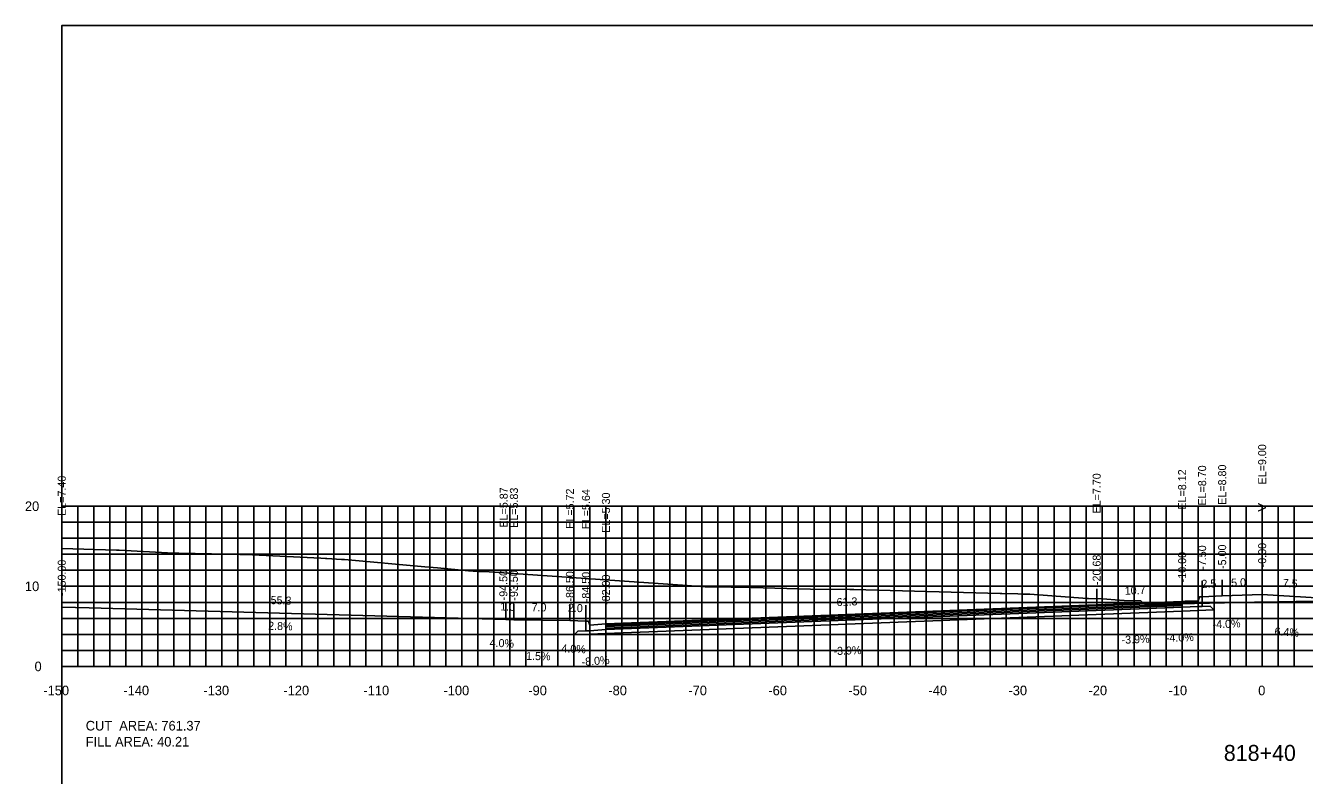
# Model space of a CAD drawing. Extents: x 1797419 to 1809236, y 248759 to 251512.
# Drawn here: x 1805536.5 to 1805696.3, y 250175.8 to 250269.4 of the extents above; entities that cross this region are included whole.
import ezdxf

# ---------------------------------------------------------------- set-up
doc = ezdxf.new("R2010")
doc.units = 0
for name, color, linetype in [('1', 7, 'Continuous'), ('10', 7, 'Continuous'), ('3', 7, 'Continuous'), ('31', 7, 'Continuous'), ('4', 7, 'Continuous'), ('60', 7, 'Continuous'), ('ANNO-TXT', 7, 'Continuous'), ('BASE', 7, 'Continuous'), ('CL-CNST', 7, 'Continuous'), ('Level 62', 7, 'Continuous'), ('LOWER BINDER', 7, 'Continuous'), ('M-ROADS', 7, 'Continuous'), ('UPPER BINDER', 7, 'Continuous'), ('WEARING', 7, 'Continuous')]:
    doc.layers.add(name, color=color, linetype=linetype)

msp = doc.modelspace()

# ---------------------------------------------------------------- linework, layer by layer
for p, q in [((1805683.5, 250198.13), (1805683.5, 250200.13)), ((1805686, 250198.23), (1805686, 250200.23)), ((1805691, 250198.43), (1805691, 250200.43)), ((1805541, 250196.83), (1805541, 250198.83)), ((1805670.32, 250197.13), (1805670.32, 250199.13)), ((1805681, 250197.55), (1805681, 250199.55)), ((1805596.5, 250195.3), (1805596.5, 250197.3)), ((1805597.5, 250195.26), (1805597.5, 250197.26)), ((1805604.5, 250195.16), (1805604.5, 250197.16)), ((1805606.5, 250195.08), (1805606.5, 250197.08)), ((1805609, 250194.74), (1805609, 250196.74))]:
    msp.add_line(p, q)
for points in [[(1805541, 250079.43), (1805841, 250079.43), (1805841, 250269.43), (1805541, 250269.43)], [(1805683.5, 250198.13), (1805683.17, 250198.13), (1805683, 250197.63), (1805681, 250197.55), (1805681, 250196.83), (1805683, 250196.91), (1805683.5, 250196.91)], [(1805609, 250194.74), (1805607, 250194.58), (1805606.84, 250195.08), (1805606.5, 250195.08), (1805606.5, 250193.86), (1805607, 250193.86), (1805609, 250194.02)]]:
    msp.add_lwpolyline(points, close=True)
at = {"layer": '60'}
for p, q in [((1805540.94, 250209.43), (1805541, 250209.43)), ((1805541, 250189.43), (1805541, 250209.43)), ((1805540.94, 250199.43), (1805541, 250199.43)), ((1805540.94, 250189.43), (1805541, 250189.43)), ((1805541, 250189.43), (1805841, 250189.43)), ((1805541, 250189.37), (1805541, 250189.43)), ((1805551, 250189.37), (1805551, 250189.43)), ((1805561, 250189.37), (1805561, 250189.43)), ((1805571, 250189.37), (1805571, 250189.43)), ((1805581, 250189.37), (1805581, 250189.43)), ((1805591, 250189.37), (1805591, 250189.43)), ((1805601, 250189.37), (1805601, 250189.43)), ((1805611, 250189.37), (1805611, 250189.43)), ((1805621, 250189.37), (1805621, 250189.43)), ((1805631, 250189.37), (1805631, 250189.43)), ((1805641, 250189.37), (1805641, 250189.43)), ((1805651, 250189.37), (1805651, 250189.43)), ((1805661, 250189.37), (1805661, 250189.43)), ((1805671, 250189.37), (1805671, 250189.43)), ((1805681, 250189.37), (1805681, 250189.43)), ((1805691, 250189.37), (1805691, 250189.43))]:
    msp.add_line(p, q, dxfattribs=at)
at = {"layer": 'BASE'}
msp.add_lwpolyline([(1805605.03, 250193.36), (1805605.5, 250193.83), (1805606.5, 250193.86), (1805607, 250193.86), (1805609, 250194.02), (1805681, 250196.83), (1805683, 250196.91), (1805683.5, 250196.91), (1805684.5, 250196.96), (1805684.97, 250196.49), (1805681, 250196.33), (1805609, 250193.52)], close=True, dxfattribs=at)
at = {"layer": 'CL-CNST'}
msp.add_lwpolyline([(1805541, 250196.84), (1805544.42, 250196.74), (1805596.5, 250195.3), (1805596.5, 250195.3), (1805596.61, 250195.3), (1805597.5, 250195.26), (1805604.5, 250195.16), (1805606.5, 250195.08), (1805606.75, 250195.08), (1805606.84, 250195.08), (1805606.97, 250194.67), (1805607, 250194.58), (1805609, 250194.74), (1805670.32, 250197.13), (1805681, 250197.55), (1805681.38, 250197.56), (1805683, 250197.63), (1805683.17, 250198.13), (1805683.5, 250198.13), (1805686, 250198.23), (1805691, 250198.43), (1805698.5, 250197.95)], dxfattribs=at)
at = {"layer": 'Level 62'}
for p, q in [((1805541, 250209.43), (1805841, 250209.43)), ((1805541, 250189.43), (1805541, 250209.43)), ((1805543, 250189.43), (1805543, 250209.43)), ((1805545, 250189.43), (1805545, 250209.43)), ((1805547, 250189.43), (1805547, 250209.43)), ((1805549, 250189.43), (1805549, 250209.43)), ((1805551, 250189.43), (1805551, 250209.43)), ((1805553, 250189.43), (1805553, 250209.43)), ((1805555, 250189.43), (1805555, 250209.43)), ((1805557, 250189.43), (1805557, 250209.43)), ((1805559, 250189.43), (1805559, 250209.43)), ((1805561, 250189.43), (1805561, 250209.43)), ((1805563, 250189.43), (1805563, 250209.43)), ((1805565, 250189.43), (1805565, 250209.43)), ((1805567, 250189.43), (1805567, 250209.43)), ((1805569, 250189.43), (1805569, 250209.43)), ((1805571, 250189.43), (1805571, 250209.43)), ((1805573, 250189.43), (1805573, 250209.43)), ((1805575, 250189.43), (1805575, 250209.43)), ((1805577, 250189.43), (1805577, 250209.43)), ((1805579, 250189.43), (1805579, 250209.43)), ((1805581, 250189.43), (1805581, 250209.43)), ((1805583, 250189.43), (1805583, 250209.43)), ((1805585, 250189.43), (1805585, 250209.43)), ((1805587, 250189.43), (1805587, 250209.43)), ((1805589, 250189.43), (1805589, 250209.43)), ((1805591, 250189.43), (1805591, 250209.43)), ((1805593, 250189.43), (1805593, 250209.43)), ((1805595, 250189.43), (1805595, 250209.43)), ((1805597, 250189.43), (1805597, 250209.43)), ((1805599, 250189.43), (1805599, 250209.43)), ((1805601, 250189.43), (1805601, 250209.43)), ((1805603, 250189.43), (1805603, 250209.43)), ((1805605, 250189.43), (1805605, 250209.43)), ((1805607, 250189.43), (1805607, 250209.43)), ((1805609, 250189.43), (1805609, 250209.43)), ((1805611, 250189.43), (1805611, 250209.43)), ((1805613, 250189.43), (1805613, 250209.43)), ((1805615, 250189.43), (1805615, 250209.43)), ((1805617, 250189.43), (1805617, 250209.43)), ((1805619, 250189.43), (1805619, 250209.43)), ((1805621, 250189.43), (1805621, 250209.43)), ((1805623, 250189.43), (1805623, 250209.43)), ((1805625, 250189.43), (1805625, 250209.43)), ((1805627, 250189.43), (1805627, 250209.43)), ((1805629, 250189.43), (1805629, 250209.43)), ((1805631, 250189.43), (1805631, 250209.43)), ((1805633, 250189.43), (1805633, 250209.43)), ((1805635, 250189.43), (1805635, 250209.43)), ((1805637, 250189.43), (1805637, 250209.43)), ((1805639, 250189.43), (1805639, 250209.43)), ((1805641, 250189.43), (1805641, 250209.43)), ((1805643, 250189.43), (1805643, 250209.43)), ((1805645, 250189.43), (1805645, 250209.43)), ((1805647, 250189.43), (1805647, 250209.43)), ((1805649, 250189.43), (1805649, 250209.43)), ((1805651, 250189.43), (1805651, 250209.43)), ((1805653, 250189.43), (1805653, 250209.43)), ((1805655, 250189.43), (1805655, 250209.43)), ((1805657, 250189.43), (1805657, 250209.43)), ((1805659, 250189.43), (1805659, 250209.43)), ((1805661, 250189.43), (1805661, 250209.43)), ((1805663, 250189.43), (1805663, 250209.43)), ((1805665, 250189.43), (1805665, 250209.43)), ((1805667, 250189.43), (1805667, 250209.43)), ((1805669, 250189.43), (1805669, 250209.43)), ((1805671, 250189.43), (1805671, 250209.43)), ((1805673, 250189.43), (1805673, 250209.43)), ((1805675, 250189.43), (1805675, 250209.43)), ((1805677, 250189.43), (1805677, 250209.43)), ((1805679, 250189.43), (1805679, 250209.43)), ((1805681, 250189.43), (1805681, 250209.43)), ((1805683, 250189.43), (1805683, 250209.43)), ((1805685, 250189.43), (1805685, 250209.43)), ((1805687, 250189.43), (1805687, 250209.43)), ((1805689, 250189.43), (1805689, 250209.43)), ((1805691, 250189.43), (1805691, 250209.43)), ((1805693, 250189.43), (1805693, 250209.43)), ((1805695, 250189.43), (1805695, 250209.43)), ((1805541, 250207.43), (1805841, 250207.43)), ((1805541, 250205.43), (1805841, 250205.43)), ((1805541, 250203.43), (1805841, 250203.43)), ((1805541, 250201.43), (1805841, 250201.43)), ((1805541, 250199.43), (1805841, 250199.43)), ((1805541, 250197.43), (1805841, 250197.43)), ((1805541, 250195.43), (1805841, 250195.43)), ((1805541, 250193.43), (1805841, 250193.43)), ((1805541, 250191.43), (1805841, 250191.43)), ((1805541, 250189.43), (1805841, 250189.43))]:
    msp.add_line(p, q, dxfattribs=at)
at = {"layer": 'LOWER BINDER'}
for points in [[(1805609, 250194.21), (1805609, 250194.4), (1805681, 250197.21), (1805681, 250197.02)], [(1805609, 250194.02), (1805609, 250194.21), (1805681, 250197.02), (1805681, 250196.83)]]:
    msp.add_lwpolyline(points, close=True, dxfattribs=at)
at = {"layer": 'M-ROADS'}
msp.add_lwpolyline([(1805541, 250204.15), (1805547.83, 250203.93), (1805547.99, 250203.93), (1805548.19, 250203.93), (1805554.97, 250203.59), (1805555.42, 250203.58), (1805555.62, 250203.58), (1805559.71, 250203.49), (1805563.27, 250203.42), (1805563.63, 250203.42), (1805563.96, 250203.41), (1805573.38, 250202.94), (1805573.94, 250202.92), (1805574.12, 250202.91), (1805575.94, 250202.77), (1805576.32, 250202.76), (1805586.36, 250201.85), (1805587.96, 250201.73), (1805591.83, 250201.38), (1805591.85, 250201.38), (1805592.39, 250201.34), (1805593.04, 250201.3), (1805593.08, 250201.3), (1805593.83, 250201.26), (1805619.14, 250199.54), (1805621.38, 250199.36), (1805621.5, 250199.36), (1805621.74, 250199.36), (1805621.86, 250199.36), (1805622.09, 250199.36), (1805627.16, 250199.29), (1805634.58, 250199.08), (1805639.47, 250199.02), (1805639.78, 250199.02), (1805639.98, 250199.02), (1805644.51, 250198.92), (1805658.24, 250198.54), (1805658.45, 250198.53), (1805660.48, 250198.48), (1805660.98, 250198.47), (1805661, 250198.47), (1805661.43, 250198.45), (1805661.44, 250198.45), (1805661.97, 250198.44), (1805669.12, 250197.9), (1805669.29, 250197.89), (1805669.31, 250197.89), (1805671.04, 250197.86), (1805673.19, 250197.71), (1805673.75, 250197.68), (1805675.85, 250197.61), (1805675.97, 250197.51), (1805676.37, 250197.14), (1805676.44, 250197.16), (1805676.44, 250197.17), (1805676.45, 250197.18), (1805676.46, 250197.19), (1805676.47, 250197.19), (1805676.48, 250197.18), (1805676.49, 250197.18), (1805676.5, 250197.18), (1805676.51, 250197.17), (1805676.53, 250197.17), (1805676.53, 250197.17), (1805676.54, 250197.16), (1805676.56, 250197.15), (1805676.57, 250197.14), (1805676.58, 250197.15), (1805676.6, 250197.16), (1805676.63, 250197.18), (1805676.63, 250197.18), (1805676.66, 250197.17), (1805676.69, 250197.16), (1805676.7, 250197.16), (1805676.72, 250197.16), (1805676.76, 250197.16), (1805676.81, 250197.16), (1805676.87, 250197.16), (1805676.93, 250197.15), (1805676.97, 250197.14), (1805677.02, 250197.15), (1805677.11, 250197.16), (1805678.79, 250197.2), (1805690.02, 250197.44), (1805690.72, 250197.45), (1805697.52, 250197.56)], dxfattribs=at)
at = {"layer": 'UPPER BINDER'}
msp.add_lwpolyline([(1805681, 250197.4), (1805609, 250194.59), (1805609, 250194.4), (1805681, 250197.21)], close=True, dxfattribs=at)
at = {"layer": 'WEARING'}
msp.add_lwpolyline([(1805681, 250197.55), (1805609, 250194.74), (1805609, 250194.59), (1805681, 250197.4)], close=True, dxfattribs=at)

# ---------------------------------------------------------------- texts
at = {"layer": '1'}
msp.add_text('818+40', height=2, dxfattribs=at).set_placement((1805686.21, 250177.63))
at = {"layer": '10'}
for s, p in [('-150', (1805538.7, 250185.83)), ('-140', (1805548.7, 250185.83)), ('-130', (1805558.7, 250185.83)), ('-120', (1805568.7, 250185.83)), ('-110', (1805578.7, 250185.83)), ('-100', (1805588.7, 250185.83)), ('-90', (1805599.3, 250185.83)), ('-80', (1805609.3, 250185.83)), ('-70', (1805619.3, 250185.83)), ('-60', (1805629.3, 250185.83)), ('-50', (1805639.3, 250185.83)), ('-40', (1805649.3, 250185.83)), ('-30', (1805659.3, 250185.83)), ('-20', (1805669.3, 250185.83)), ('-10', (1805679.3, 250185.83)), ('0', (1805690.5, 250185.83))]:
    msp.add_text(s, height=1.2, dxfattribs=at).set_placement(p)
at = {"layer": '3'}
for s, p in [('EL=9.00', (1805691.5, 250212.15)), ('EL=8.80', (1805686.5, 250209.61)), ('EL=7.40', (1805541.5, 250208.22)), ('EL=7.70', (1805670.82, 250208.52)), ('EL=8.12', (1805681.5, 250209.01)), ('EL=8.70', (1805684, 250209.51)), ('EL=5.87', (1805596.72, 250206.77)), ('EL=5.83', (1805598, 250206.73)), ('EL=5.72', (1805605, 250206.62)), ('EL=5.64', (1805607, 250206.54)), ('EL=5.30', (1805609.5, 250206.12)), ('-20.68', (1805670.82, 250199.59)), ('-10.00', (1805681.5, 250199.93)), ('-7.50', (1805684, 250201.5)), ('-5.00', (1805686.5, 250201.6)), ('-0.00', (1805691.5, 250201.8)), ('-150.00', (1805541.5, 250198.22)), ('-94.50', (1805596.68, 250197.68)), ('-93.50', (1805598, 250197.64)), ('-86.50', (1805605, 250197.53)), ('-84.50', (1805607, 250197.45)), ('-82.00', (1805609.5, 250197.11))]:
    msp.add_text(s, height=1, rotation=90, dxfattribs=at).set_placement(p)
at = {"layer": '31'}
for s, p in [('20', (1805536.4, 250208.83)), ('10', (1805536.4, 250198.83)), ('0', (1805537.6, 250188.83))]:
    msp.add_text(s, height=1.2, dxfattribs=at).set_placement(p)
at = {"layer": '4'}
for s, rotation, p in [('2.5', 2.2906, (1805683.43, 250199.23)), ('5.0', 2.2906, (1805687.14, 250199.38)), ('7.5', 356.3612, (1805693.54, 250199.37)), ('10.7', 2.2381, (1805673.84, 250198.37)), ('55.3', 358.4206, (1805567.09, 250197.21)), ('1.0', 357.7098, (1805595.78, 250196.43)), ('7.0', 359.1407, (1805599.7, 250196.33)), ('2.0', 357.7091, (1805604.23, 250196.27)), ('61.3', 2.2381, (1805637.84, 250196.96)), ('2.8%', 358.4206, (1805566.78, 250194.01)), ('-4.0%', 2.2906, (1805684.82, 250194.17)), ('6.4%', 356.3612, (1805692.52, 250193.32)), ('4.0%', 357.7098, (1805594.45, 250191.9)), ('4.0%', 357.7098, (1805603.42, 250191.19)), ('-3.9%', 2.2381, (1805673.45, 250192.25)), ('-4.0%', 2.2623, (1805678.98, 250192.47)), ('1.5%', 359.1407, (1805599.02, 250190.24)), ('-8.0%', 4.5746, (1805606, 250189.48)), ('-3.9%', 2.2381, (1805637.45, 250190.84))]:
    msp.add_text(s, height=1, rotation=rotation, dxfattribs=at).set_placement(p)
at = {"layer": '60'}
for s, height, p in [('>', 1.5, (1805690.39, 250208.57)), ('-', 0.0001, (1805541, 250189.43))]:
    msp.add_text(s, height=height, dxfattribs=at).set_placement(p)
at = {"layer": 'ANNO-TXT'}
for s, p in [('CUT  AREA: 761.37', (1805544, 250181.43)), ('FILL AREA: 40.21', (1805544, 250179.43))]:
    msp.add_text(s, height=1.2, dxfattribs=at).set_placement(p)

doc.saveas('drawing.dxf')
